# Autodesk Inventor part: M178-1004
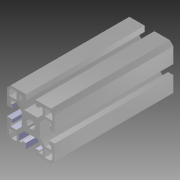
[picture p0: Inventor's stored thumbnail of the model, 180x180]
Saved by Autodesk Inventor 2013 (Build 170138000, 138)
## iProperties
Created: 2004-10
Material: Aluminium - 6061
Document SubType Name: Modeling
Designer: Autodesk, Inc.
Manufacturer: Standard
Standards Organization: Custom
Description: TABLE, LEG
Stock Number: 10-040
Catalog Web Link: http://www.parker.com/ead/cm1.asp?cmid=809
Vendor: PARKER IPS
Part Number: M178-1004
Mass: 179.948 g
Surface Area: 483.565 cm^2
Volume: 66.4013 cm^3
Density: 2.71 g/cm^3
CAGE: 1LJX3
Dept. ID: Product Design
Description #2: ---
Finish #1: ---
Finish #2: ---
Material ID: ---
Project Number: ---
Length: 812.800 mm
Author: Autodesk, Inc.
Revision Number: A
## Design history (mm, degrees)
derived "40 Series Profiles.ipt"
thread "Thread1" dims "d9" = 50, "d10" = 0
feature "IPS40SeriesCutout1"
body "Solid1"
tag "TaggingFeature2"
sketch "Sketch1"
  geometry: L1 (7, -456.4)-(28, -456.4) reference; L2 (28, 356.4)-(28, -456.4) reference; L3 (20, -456.4)-(20, 356.4) reference; L4 (28, -436.4)-(20, -436.4); C1 r 10 at (24, -436.4)
  constraints: 2 end point, 2 point on line, 1 centre point, 1 midpoint, 1 perpendicular
  dimensions: "d11" = 20 distance between parallel lines of L4 L1; "d12" = 20 diameter of C1
feature "Solid1::40 Series Profiles.ipt" dims "ScaleForDerivedMember" = 10
other parameters: "Length" = 812.8
